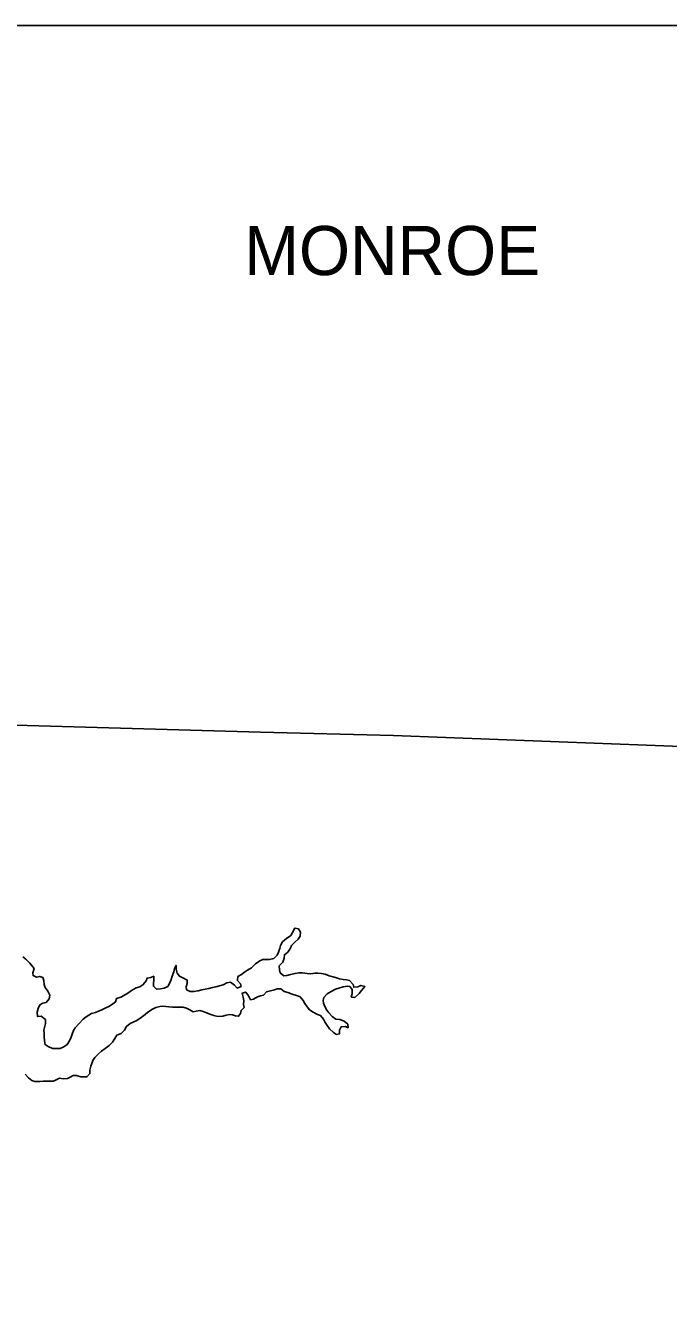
# Model space of a CAD drawing. Extents: x -29.6 to 34, y 0 to 22.
# Drawn here: x -20.183 to -18.092, y 9.088 to 13.208 of the extents above; entities that cross this region are included whole.
import ezdxf

# ---------------------------------------------------------------- set-up
doc = ezdxf.new("R2010")
doc.units = 0
for name, color, linetype in [('GM_X_Major_Lake', 7, 'Continuous'), ('GM_X_Township', 7, 'Continuous'), ('GM_X_Township_Text', 7, 'Continuous'), ('SH_Text', 7, 'Continuous')]:
    doc.layers.add(name, color=color, linetype=linetype)

msp = doc.modelspace()

# ---------------------------------------------------------------- linework, layer by layer
at = {"layer": 'GM_X_Major_Lake'}
for points in [[(-19.1347, 9.9602), (-19.1459, 9.9704), (-19.1608, 9.9756), (-19.1733, 9.9766), (-19.1858, 9.9854), (-19.1966, 9.997), (-19.2027, 10.0063), (-19.2089, 10.0176), (-19.2133, 10.0283), (-19.2141, 10.0375), (-19.2124, 10.0468), (-19.2012, 10.0594), (-19.1888, 10.067), (-19.175, 10.0743), (-19.1633, 10.0776), (-19.1495, 10.0824), (-19.1371, 10.0839), (-19.1275, 10.0829), (-19.1203, 10.0734), (-19.1208, 10.0605), (-19.1236, 10.0487), (-19.1122, 10.0474), (-19.0974, 10.06), (-19.0897, 10.0701), (-19.0795, 10.0834), (-19.092, 10.0865), (-19.1022, 10.0814), (-19.115, 10.0805), (-19.1172, 10.0898), (-19.1287, 10.1022), (-19.1383, 10.1042), (-19.1497, 10.1062), (-19.1618, 10.1076), (-19.1715, 10.1107), (-19.1822, 10.1145), (-19.1953, 10.1176), (-19.2082, 10.1232), (-19.221, 10.1252), (-19.2317, 10.1262), (-19.242, 10.1261), (-19.2544, 10.1245), (-19.2662, 10.1258), (-19.2822, 10.1278), (-19.2935, 10.1277), (-19.306, 10.1258), (-19.3205, 10.1217), (-19.3326, 10.1191), (-19.3421, 10.1176), (-19.354, 10.1271), (-19.3569, 10.1375), (-19.3574, 10.1503), (-19.3461, 10.1622), (-19.3416, 10.1747), (-19.3407, 10.1861), (-19.3294, 10.1951), (-19.321, 10.2073), (-19.3179, 10.2166), (-19.3077, 10.2263), (-19.2961, 10.2372), (-19.2898, 10.2468), (-19.2878, 10.2593), (-19.2943, 10.2703), (-19.3064, 10.2727), (-19.3141, 10.2591), (-19.3193, 10.2491), (-19.3341, 10.2396), (-19.3472, 10.2278), (-19.3531, 10.2163), (-19.3551, 10.2074), (-19.36, 10.1948), (-19.3638, 10.1852), (-19.3751, 10.174), (-19.3892, 10.1707), (-19.3992, 10.1713), (-19.4102, 10.1705), (-19.4205, 10.1668), (-19.4342, 10.1567), (-19.448, 10.1437), (-19.4607, 10.1361), (-19.4699, 10.13), (-19.4797, 10.1224), (-19.4917, 10.1151), (-19.493, 10.1026), (-19.4837, 10.092), (-19.4815, 10.0831), (-19.4946, 10.0777), (-19.5032, 10.0876), (-19.5154, 10.0974), (-19.5282, 10.0948), (-19.5395, 10.0883), (-19.5519, 10.085), (-19.5639, 10.082), (-19.5746, 10.0794), (-19.5863, 10.0768), (-19.5983, 10.0746), (-19.609, 10.0727), (-19.621, 10.0693), (-19.6349, 10.0667), (-19.6466, 10.067), (-19.6587, 10.0722), (-19.6602, 10.0815)], [(-20.1679, 10.1591), (-20.1808, 10.1714), (-20.1912, 10.1792)], [(-20.094, 9.8812), (-20.1082, 9.8878), (-20.1186, 9.8941), (-20.1205, 9.9062), (-20.1213, 9.9201), (-20.1217, 9.9311), (-20.1222, 9.9407), (-20.1198, 9.9535), (-20.1167, 9.9631), (-20.1171, 9.9756), (-20.1307, 9.9869), (-20.1427, 9.9854), (-20.1443, 9.9996), (-20.1415, 10.0117), (-20.136, 10.0231), (-20.1257, 10.0289), (-20.1154, 10.0311), (-20.1052, 10.0426), (-20.1028, 10.0543), (-20.1093, 10.0681), (-20.1183, 10.0802), (-20.1212, 10.0897), (-20.1227, 10.1022), (-20.1257, 10.1118), (-20.1356, 10.1156), (-20.1466, 10.1134), (-20.1573, 10.1186), (-20.1581, 10.1279), (-20.1543, 10.1418), (-20.1679, 10.1591)], [(-19.6602, 10.0815), (-19.6568, 10.0925), (-19.6566, 10.104), (-19.6708, 10.1109), (-19.6819, 10.1162), (-19.6888, 10.1268), (-19.6928, 10.1396), (-19.6929, 10.1514), (-19.6975, 10.1417), (-19.7002, 10.1303), (-19.705, 10.1163), (-19.7088, 10.106), (-19.7126, 10.0949), (-19.72, 10.0827), (-19.7309, 10.0779), (-19.743, 10.0757), (-19.7565, 10.0741), (-19.7662, 10.0837), (-19.7666, 10.0929), (-19.7646, 10.1044), (-19.7654, 10.1165), (-19.7746, 10.1118), (-19.7867, 10.1102), (-19.7898, 10.1009), (-19.7996, 10.0894), (-19.8109, 10.0818), (-19.8226, 10.0789), (-19.8371, 10.0705), (-19.8495, 10.0615), (-19.8625, 10.0535), (-19.8724, 10.0481), (-19.8866, 10.0437), (-19.8901, 10.0329), (-19.9024, 10.0235), (-19.9116, 10.0181), (-19.9208, 10.0141), (-19.936, 10.0065), (-19.9452, 10.0028), (-19.9548, 9.9988), (-19.9679, 9.9948), (-19.9848, 9.9843), (-19.9943, 9.9763), (-20.0088, 9.9616), (-20.0207, 9.9486), (-20.0256, 9.9397), (-20.0305, 9.9282), (-20.0339, 9.9178), (-20.0391, 9.9067), (-20.0472, 9.8949), (-20.0574, 9.8866), (-20.0694, 9.8811), (-20.0822, 9.8814), (-20.094, 9.8812)], [(-20.0908, 9.7757), (-20.072, 9.7845), (-20.0592, 9.7824), (-20.0457, 9.784), (-20.0365, 9.7884), (-20.0273, 9.7934), (-20.0167, 9.7932), (-20.0028, 9.7898), (-19.9924, 9.7888), (-19.9825, 9.7892), (-19.973, 9.7997), (-19.9728, 9.8114), (-19.97, 9.8236), (-19.9669, 9.8329), (-19.9635, 9.8422), (-19.9565, 9.8522), (-19.9445, 9.8645), (-19.935, 9.8731), (-19.9234, 9.8811), (-19.9107, 9.8908), (-19.8998, 9.9016), (-19.8917, 9.9138), (-19.8854, 9.9246), (-19.8716, 9.9304), (-19.8607, 9.9409), (-19.8544, 9.953), (-19.8417, 9.9628), (-19.8297, 9.9679), (-19.8201, 9.973), (-19.8067, 9.982), (-19.7937, 9.9921), (-19.7845, 9.9993), (-19.7697, 10.0095), (-19.7587, 10.0146), (-19.7453, 10.0179), (-19.7353, 10.0191), (-19.7168, 10.0167), (-19.7044, 10.0158), (-19.694, 10.0159), (-19.6827, 10.0163), (-19.6706, 10.0154), (-19.6585, 10.0127), (-19.6481, 10.007), (-19.6374, 10.0004), (-19.6271, 10.0026), (-19.6154, 10.0045), (-19.6043, 10.0018), (-19.5933, 9.9972), (-19.5797, 9.992), (-19.5697, 9.9889), (-19.5608, 9.9861), (-19.5519, 9.9851), (-19.5406, 9.987), (-19.5299, 9.99), (-19.5182, 9.9915), (-19.509, 9.9905), (-19.4997, 9.9878), (-19.4894, 9.9864), (-19.4834, 9.9954), (-19.4814, 10.0051), (-19.4712, 10.0151), (-19.4731, 10.0244), (-19.4728, 10.0369), (-19.4751, 10.0483), (-19.478, 10.0611), (-19.466, 10.0651), (-19.4577, 10.0527), (-19.4505, 10.0399), (-19.4412, 10.0418), (-19.4282, 10.0491), (-19.4186, 10.0527), (-19.409, 10.0549), (-19.3988, 10.0657), (-19.3854, 10.0691), (-19.373, 10.0724), (-19.3637, 10.0753), (-19.3524, 10.0751), (-19.3409, 10.0666), (-19.3291, 10.0635), (-19.3152, 10.0576), (-19.2985, 10.0531), (-19.2896, 10.0493), (-19.2791, 10.038), (-19.2744, 10.0277), (-19.2665, 10.0167), (-19.2586, 10.0075), (-19.2475, 9.9994), (-19.2328, 9.9924), (-19.2235, 9.9882), (-19.2131, 9.9766), (-19.2077, 9.9663), (-19.2015, 9.9567), (-19.1943, 9.945), (-19.1814, 9.9334), (-19.1717, 9.9267), (-19.1618, 9.9286), (-19.1612, 9.9414), (-19.156, 9.9521), (-19.1425, 9.953), (-19.1336, 9.9491)], [(-20.0908, 9.7757), (-20.072, 9.7845), (-20.0592, 9.7824), (-20.0457, 9.784), (-20.0365, 9.7884), (-20.0273, 9.7934), (-20.0167, 9.7932), (-20.0028, 9.7898), (-19.9924, 9.7888), (-19.9825, 9.7892), (-19.973, 9.7997), (-19.9728, 9.8114), (-19.97, 9.8236), (-19.9669, 9.8329), (-19.9635, 9.8422), (-19.9565, 9.8522), (-19.9445, 9.8645), (-19.935, 9.8731), (-19.9234, 9.8811), (-19.9107, 9.8908), (-19.8998, 9.9016), (-19.8917, 9.9138), (-19.8854, 9.9246), (-19.8716, 9.9304), (-19.8607, 9.9409), (-19.8544, 9.953), (-19.8417, 9.9628), (-19.8297, 9.9679), (-19.8201, 9.973), (-19.8067, 9.982), (-19.7937, 9.9921), (-19.7845, 9.9993), (-19.7697, 10.0095), (-19.7587, 10.0146), (-19.7453, 10.0179), (-19.7353, 10.0191), (-19.7168, 10.0167), (-19.7044, 10.0158), (-19.694, 10.0159), (-19.6827, 10.0163), (-19.6706, 10.0154), (-19.6585, 10.0127), (-19.6481, 10.007), (-19.6374, 10.0004), (-19.6271, 10.0026), (-19.6154, 10.0045), (-19.6043, 10.0018), (-19.5933, 9.9972), (-19.5797, 9.992), (-19.5697, 9.9889), (-19.5608, 9.9861), (-19.5519, 9.9851), (-19.5406, 9.987), (-19.5299, 9.99), (-19.5182, 9.9915), (-19.509, 9.9905), (-19.4997, 9.9878), (-19.4894, 9.9864), (-19.4834, 9.9954), (-19.4814, 10.0051), (-19.4712, 10.0151), (-19.4731, 10.0244), (-19.4728, 10.0369), (-19.4751, 10.0483), (-19.478, 10.0611), (-19.466, 10.0651), (-19.4577, 10.0527), (-19.4505, 10.0399), (-19.4412, 10.0418), (-19.4282, 10.0491), (-19.4186, 10.0527), (-19.409, 10.0549), (-19.3988, 10.0657), (-19.3854, 10.0691), (-19.373, 10.0724), (-19.3637, 10.0753), (-19.3524, 10.0751), (-19.3409, 10.0666), (-19.3291, 10.0635), (-19.3152, 10.0576), (-19.2985, 10.0531), (-19.2896, 10.0493), (-19.2791, 10.038), (-19.2744, 10.0277), (-19.2665, 10.0167), (-19.2586, 10.0075), (-19.2475, 9.9994), (-19.2328, 9.9924), (-19.2235, 9.9882), (-19.2131, 9.9766), (-19.2077, 9.9663), (-19.2015, 9.9567), (-19.1943, 9.945), (-19.1814, 9.9334), (-19.1717, 9.9267), (-19.1618, 9.9286), (-19.1612, 9.9414), (-19.156, 9.9521), (-19.1425, 9.953), (-19.1336, 9.9492), (-19.1347, 9.9602)], [(-19.1336, 9.9491), (-19.1347, 9.9602)], [(-20.1828, 9.7983), (-20.172, 9.7859), (-20.162, 9.7771), (-20.1521, 9.774), (-20.1361, 9.7745), (-20.1247, 9.7749), (-20.1084, 9.7751), (-20.0908, 9.7757)]]:
    msp.add_lwpolyline(points, dxfattribs=at)
at = {"layer": 'GM_X_Township'}
msp.add_lwpolyline([(-17.8742, 6.1253), (-19.1572, 6.1651), (-20.7391, 6.2042), (-21.4075, 6.2188), (-21.6713, 6.2244), (-21.6682, 6.402), (-21.6504, 7.1784), (-21.6499, 7.2446), (-21.6214, 8.5068), (-21.5392, 10.9421), (-21.5395, 10.9431), (-21.5399, 10.9443), (-21.5403, 10.9462), (-21.5405, 10.9479), (-21.5406, 10.9493), (-21.5407, 10.956), (-21.5408, 10.9609), (-21.5413, 10.9689), (-21.5414, 10.9701), (-19.4178, 10.9099), (-18.9861, 10.8993), (-17.4554, 10.8405)], dxfattribs=at)
at = {"layer": 'SH_Text'}
msp.add_lwpolyline([(-29.5833, 13.2079), (-10.7478, 13.2079), (-10.7478, 1.0528), (-29.5833, 1.0528)], close=True, dxfattribs=at)

# ---------------------------------------------------------------- texts
at = {"layer": 'GM_X_Township_Text'}
msp.add_text('MONROE', height=0.1598, rotation=0, dxfattribs=at).set_placement((-19.4714, 12.3959))

doc.saveas('drawing.dxf')
